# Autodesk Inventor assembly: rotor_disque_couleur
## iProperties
Created: 2011-01
Part Number: rotor_disque_couleur
Document SubType Name: Assembly
Designer: eric
Mass: 13.5158 g
Surface Area: 233.568 cm^2
Volume: 13.5158 cm^3
Density: 1 g/cm^3
Norme de conversion: IGES 5.3
Nom du fichier: No Iges File Name specified
Préprocesseur: Autodesk Inventor 2011
Postprocesseur: Build: 342, Release: 2008 SP3 - Date: Tue 05/27/2008
Unités envoyées: MM
Incertitude: 0.01
Author: eric
